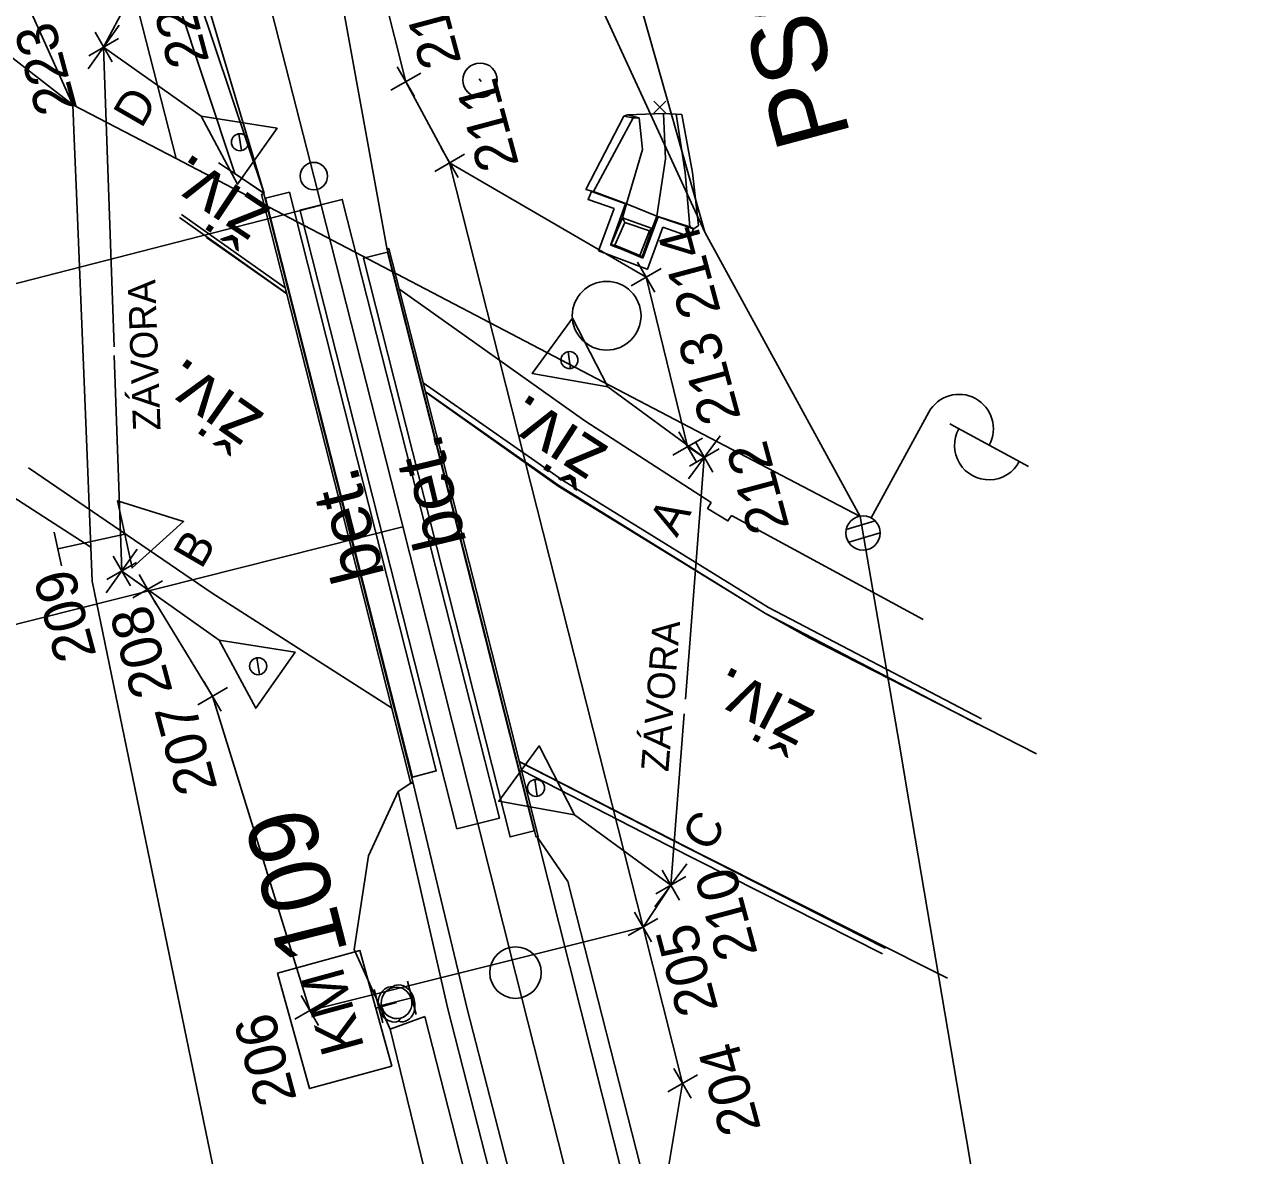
# Model space of a CAD drawing. Extents: x -754679 to -754173, y -1169241 to -1168288.
# Drawn here: x -754521.78 to -754486.32, y -1168479.14 to -1168446.2 of the extents above; entities that cross this region are included whole.
import ezdxf

# ---------------------------------------------------------------- set-up
doc = ezdxf.new("R2010")
doc.units = 0
for name, color, linetype in [('Vrstva 1', 7, 'Continuous'), ('Vrstva 11', 7, 'Continuous'), ('Vrstva 12', 7, 'Continuous'), ('Vrstva 16', 7, 'Continuous'), ('Vrstva 19', 7, 'Continuous'), ('Vrstva 25', 7, 'Continuous'), ('Vrstva 3', 7, 'Continuous'), ('Vrstva 36', 7, 'Continuous'), ('Vrstva 4', 7, 'Continuous'), ('Vrstva 43', 7, 'Continuous'), ('Vrstva 45', 7, 'Continuous'), ('Vrstva 49', 7, 'Continuous'), ('Vrstva 51', 7, 'Continuous'), ('Vrstva 53', 7, 'Continuous'), ('Vrstva 55', 7, 'Continuous'), ('Vrstva 6', 7, 'Continuous'), ('Vrstva 60', 7, 'Continuous'), ('Vrstva 7', 7, 'Continuous')]:
    doc.layers.add(name, color=color, linetype=linetype)

msp = doc.modelspace()

# ---------------------------------------------------------------- linework, layer by layer
at = {"layer": 'Vrstva 1'}
msp.add_line((-754513.137, -1168451.466), (-754513.352, -1168450.618), dxfattribs=at)
for points in [[(-754513.352, -1168450.618), (-754515.29, -1168443.036), (-754517.542, -1168434.317), (-754517.919, -1168432.843), (-754519.829, -1168425.595), (-754522.159, -1168416.85), (-754524.525, -1168408.114), (-754526.908, -1168399.431), (-754528.183, -1168394.853), (-754528.892, -1168392.323), (-754531.158, -1168384.271), (-754532.075, -1168381.055)], [(-754519.168, -1168455.593), (-754519.47, -1168446.863)], [(-754498.393, -1168509.746), (-754500.095, -1168502.999), (-754500.372, -1168501.892), (-754500.594, -1168501.052), (-754502.803, -1168492.326), (-754502.981, -1168491.622), (-754505.012, -1168483.589), (-754507.469, -1168473.859), (-754508.579, -1168469.465), (-754510.811, -1168460.627), (-754513.137, -1168451.466)], [(-754518.943, -1168462.117), (-754519.16, -1168455.846)], [(-754502.538, -1168465.845), (-754501.988, -1168458.809)], [(-754502.962, -1168471.262), (-754502.572, -1168466.271)]]:
    msp.add_lwpolyline(points, dxfattribs=at)
msp.add_circle((-754513.352, -1168450.618), 0.4, dxfattribs=at)
at = {"layer": 'Vrstva 11'}
for p, q in [((-754510.623, -1168474.056), (-754510.378, -1168475.025)), ((-754511.592, -1168474.301), (-754511.347, -1168475.27)), ((-754510.5, -1168474.54), (-754511.47, -1168474.786))]:
    msp.add_line(p, q, dxfattribs=at)
at = {"layer": 'Vrstva 12'}
for p, q in [((-754511.066, -1168474.219), (-754511.047, -1168474.24)), ((-754511.379, -1168474.792), (-754511.468, -1168474.812)), ((-754510.441, -1168474.553), (-754510.512, -1168474.574)), ((-754510.887, -1168475.224), (-754510.832, -1168475.134))]:
    msp.add_line(p, q, dxfattribs=at)
for centre, major_axis, ratio, start_param, end_param in [((-754510.835, -1168474.701), (0.12, -0.53), 0.771425, 5.875182, 9.712717), ((-754511.047, -1168474.732), (-0.119, 0.504), 0.826855, 6.048062, 9.524036), ((-754510.932, -1168474.685), (0.273, -0.37), 0.999682, 2.76009, 5.867568), ((-754510.957, -1168474.691), (-0.275, -0.369), 0.999919, 0.916275, 3.979936)]:
    msp.add_ellipse(centre, major_axis=major_axis, ratio=ratio, start_param=start_param, end_param=end_param, dxfattribs=at)
at = {"layer": 'Vrstva 16'}
for p, q in [((-754511.127, -1168475.454), (-754512.179, -1168473.131)), ((-754511.127, -1168475.454), (-754510.126, -1168475.086)), ((-754510.126, -1168475.086), (-754505.572, -1168492.818)), ((-754506.811, -1168493.205), (-754511.127, -1168475.454))]:
    msp.add_line(p, q, dxfattribs=at)
msp.add_lwpolyline([(-754512.179, -1168473.131), (-754511.761, -1168470.408), (-754510.894, -1168468.538)], dxfattribs=at)
at = {"layer": 'Vrstva 19'}
for p, q in [((-754505.44, -1168451.004), (-754504.327, -1168448.871)), ((-754505.208, -1168451.063), (-754504.058, -1168448.925)), ((-754504.327, -1168448.871), (-754504.222, -1168448.832)), ((-754504.058, -1168448.925), (-754504.327, -1168448.871)), ((-754503.175, -1168448.797), (-754504.222, -1168448.832)), ((-754504.222, -1168448.832), (-754503.885, -1168448.92)), ((-754504.058, -1168448.925), (-754503.885, -1168448.92)), ((-754503.783, -1168449.845), (-754503.885, -1168448.92)), ((-754502.806, -1168448.814), (-754503.175, -1168448.797)), ((-754503.115, -1168450.12), (-754503.175, -1168448.797)), ((-754502.64, -1168448.824), (-754503.175, -1168448.797)), ((-754502.549, -1168450.509), (-754502.806, -1168448.814)), ((-754502.64, -1168448.824), (-754502.806, -1168448.814)), ((-754502.334, -1168450.518), (-754502.64, -1168448.824)), ((-754504.248, -1168451.425), (-754503.783, -1168449.845)), ((-754503.368, -1168451.781), (-754503.115, -1168450.12)), ((-754502.41, -1168452.1), (-754502.549, -1168450.509)), ((-754502.161, -1168452.059), (-754502.334, -1168450.518)), ((-754505.272, -1168451.065), (-754505.292, -1168451.049)), ((-754505.208, -1168451.063), (-754504.248, -1168451.425)), ((-754513.137, -1168451.466), (-754572.704, -1168466.762)), ((-754504.367, -1168451.831), (-754504.248, -1168451.425)), ((-754504.286, -1168451.422), (-754504.248, -1168451.425)), ((-754505.069, -1168452.793), (-754504.616, -1168451.557)), ((-754503.33, -1168451.806), (-754503.368, -1168451.781)), ((-754502.41, -1168452.1), (-754503.368, -1168451.781)), ((-754504.367, -1168451.831), (-754504.298, -1168451.971)), ((-754503.644, -1168453.331), (-754503.196, -1168452.104)), ((-754503.506, -1168452.14), (-754503.582, -1168452.211)), ((-754502.307, -1168452.158), (-754502.288, -1168452.149)), ((-754504.706, -1168452.607), (-754503.78, -1168453.009)), ((-754504.706, -1168452.607), (-754504.704, -1168452.627)), ((-754504.704, -1168452.627), (-754504.595, -1168452.631))]:
    msp.add_line(p, q, dxfattribs=at)
for points in [[(-754505.208, -1168451.063), (-754505.292, -1168451.049), (-754505.44, -1168451.004)], [(-754504.616, -1168451.557), (-754505.371, -1168451.304), (-754505.272, -1168451.065), (-754504.286, -1168451.422), (-754504.706, -1168452.607)], [(-754503.506, -1168452.14), (-754503.368, -1168451.781), (-754504.248, -1168451.425)], [(-754503.78, -1168453.009), (-754503.33, -1168451.806), (-754502.307, -1168452.158), (-754502.401, -1168452.389), (-754502.402, -1168452.389), (-754503.196, -1168452.104)], [(-754504.704, -1168452.627), (-754504.367, -1168451.831), (-754503.506, -1168452.14), (-754503.799, -1168452.967), (-754504.704, -1168452.627)], [(-754504.595, -1168452.631), (-754504.298, -1168451.971), (-754503.582, -1168452.211), (-754503.863, -1168452.93), (-754504.209, -1168452.783), (-754504.595, -1168452.631)], [(-754502.41, -1168452.1), (-754502.288, -1168452.149), (-754502.161, -1168452.059)], [(-754505.069, -1168452.793), (-754503.65, -1168453.33), (-754503.644, -1168453.331)], [(-754503.78, -1168453.009), (-754503.799, -1168452.967), (-754503.863, -1168452.93)]]:
    msp.add_lwpolyline(points, dxfattribs=at)
at = {"layer": 'Vrstva 25'}
for p, q in [((-754497.128, -1168460.568), (-754495.455, -1168457.494)), ((-754494.84, -1168457.828), (-754492.556, -1168459.071)), ((-754497.857, -1168460.907), (-754497.013, -1168460.658)), ((-754497.786, -1168461.277), (-754496.868, -1168461.006))]:
    msp.add_line(p, q, dxfattribs=at)
msp.add_circle((-754497.367, -1168461.007), 0.5, dxfattribs=at)
for centre, start, end in [((-754494.576, -1168457.972), 331.4393, 151.4393), ((-754493.704, -1168458.461), 150.7367, 332.1418)]:
    msp.add_arc(centre, 1, start, end, dxfattribs=at)
at = {"layer": 'Vrstva 36'}
msp.add_line((-754508.542, -1168447.784), (-754508.486, -1168447.868), dxfattribs=at)
msp.add_circle((-754508.514, -1168447.826), 0.5, dxfattribs=at)
at = {"layer": 'Vrstva 4'}
for p, q in [((-754515.654, -1168450.546), (-754518.061, -1168443.282)), ((-754517.46, -1168443.166), (-754514.802, -1168451.124)), ((-754514.802, -1168451.124), (-754517.175, -1168443.155)), ((-754511.222, -1168452.767), (-754512.57, -1168445.306)), ((-754519.019, -1168446.229), (-754519.921, -1168447.497)), ((-754515.539, -1168449.392), (-754515.46, -1168449.875)), ((-754514.802, -1168451.124), (-754515.654, -1168450.546)), ((-754505.878, -1168456.217), (-754505.949, -1168455.733)), ((-754502.449, -1168459.435), (-754501.527, -1168458.183)), ((-754510.761, -1168460.826), (-754571.045, -1168476.051)), ((-754518.492, -1168461.483), (-754519.394, -1168462.751)), ((-754515.011, -1168464.645), (-754514.932, -1168465.128)), ((-754510.894, -1168468.538), (-754510.47, -1168468.256)), ((-754508.877, -1168474.898), (-754510.47, -1168468.256)), ((-754506.852, -1168468.67), (-754506.923, -1168468.186)), ((-754509.455, -1168474.862), (-754510.894, -1168468.538)), ((-754501.401, -1168491.431), (-754506.855, -1168469.858)), ((-754505.958, -1168471.152), (-754506.855, -1168469.858)), ((-754503.423, -1168471.888), (-754502.501, -1168470.636)), ((-754500.851, -1168491.229), (-754505.958, -1168471.152)), ((-754504.93, -1168492.552), (-754509.455, -1168474.862)), ((-754508.877, -1168474.898), (-754504.388, -1168492.293))]:
    msp.add_line(p, q, dxfattribs=at)
for points in [[(-754519.47, -1168446.863), (-754516.631, -1168448.871), (-754514.424, -1168449.224), (-754515.573, -1168450.858), (-754516.631, -1168448.871)], [(-754514.064, -1168451.087), (-754514.759, -1168451.264), (-754514.759, -1168451.265), (-754510.485, -1168468.114), (-754509.79, -1168467.936), (-754514.064, -1168451.087)], [(-754510.525, -1168468.304), (-754510.462, -1168468.293), (-754512.507, -1168460.209), (-754514.812, -1168451.138), (-754514.871, -1168451.152), (-754512.595, -1168460.123), (-754510.525, -1168468.304)], [(-754509.192, -1168469.618), (-754507.951, -1168469.31), (-754512.524, -1168451.299), (-754513.757, -1168451.606), (-754513.753, -1168451.627), (-754509.192, -1168469.618)], [(-754511.21, -1168452.835), (-754511.91, -1168453.004), (-754507.639, -1168469.854), (-754506.942, -1168469.68), (-754511.21, -1168452.835)], [(-754506.88, -1168469.859), (-754506.819, -1168469.846), (-754508.622, -1168462.701), (-754511.166, -1168452.727), (-754511.217, -1168452.745), (-754508.693, -1168462.685), (-754506.88, -1168469.859)], [(-754501.988, -1168458.809), (-754504.794, -1168456.756), (-754506.996, -1168456.367), (-754505.82, -1168454.752), (-754504.794, -1168456.756)], [(-754518.943, -1168462.117), (-754516.104, -1168464.124), (-754513.896, -1168464.476), (-754515.044, -1168466.111), (-754516.104, -1168464.124)], [(-754502.962, -1168471.262), (-754505.768, -1168469.209), (-754507.97, -1168468.82), (-754506.794, -1168467.205), (-754505.768, -1168469.209)]]:
    msp.add_lwpolyline(points, dxfattribs=at)
for centre in [(-754515.501, -1168449.633), (-754505.912, -1168455.975), (-754514.973, -1168464.886), (-754506.886, -1168468.428)]:
    msp.add_circle(centre, 0.248, dxfattribs=at)
at = {"layer": 'Vrstva 43'}
msp.add_circle((-754504.83, -1168454.685), 1, dxfattribs=at)
at = {"layer": 'Vrstva 45'}
msp.add_line((-754503.77, -1168472.48), (-754502.962, -1168471.262), dxfattribs=at)
for points in [[(-754519.47, -1168446.863), (-754518.79, -1168445.56), (-754518.97, -1168444.66), (-754520.27, -1168437.46), (-754528.21, -1168417.88), (-754526.42, -1168417.16), (-754519.52, -1168415.85), (-754514.96, -1168430.83), (-754510.674, -1168447.87), (-754509.4, -1168450.23)], [(-754503.77, -1168472.48), (-754509.4, -1168450.23)], [(-754509.4, -1168450.23), (-754503.68, -1168453.56), (-754502.475, -1168458.494), (-754501.988, -1168458.809)], [(-754518.943, -1168462.117), (-754518.19, -1168462.65), (-754516.3, -1168465.76), (-754513.47, -1168474.91), (-754503.77, -1168472.48)], [(-754503.77, -1168472.48), (-754502.62, -1168477.03), (-754503.11, -1168479.94), (-754501.32, -1168488.67), (-754499.51, -1168488.21)]]:
    msp.add_lwpolyline(points, dxfattribs=at)
at = {"layer": 'Vrstva 49'}
for p, q in [((-754503.46, -1168448.437), (-754503.106, -1168448.791)), ((-754503.46, -1168448.791), (-754503.106, -1168448.437))]:
    msp.add_line(p, q, dxfattribs=at)
at = {"layer": 'Vrstva 51'}
for p, q in [((-754514.831, -1168451.097), (-754516.13, -1168450.231)), ((-754514.831, -1168451.097), (-754514.812, -1168451.138)), ((-754501.194, -1168460.498), (-754495.622, -1168463.531)), ((-754520.912, -1168460.982), (-754520.7, -1168461.96))]:
    msp.add_line(p, q, dxfattribs=at)
for points in [[(-754517.203, -1168451.737), (-754514.186, -1168453.871), (-754514.18, -1168453.875)], [(-754514.139, -1168454.038), (-754514.159, -1168454.024), (-754517.267, -1168451.823)], [(-754514.134, -1168454.056), (-754514.143, -1168454.05), (-754516.478, -1168452.408)], [(-754501.194, -1168460.498), (-754501.303, -1168460.657), (-754501.894, -1168460.295), (-754501.793, -1168460.124), (-754505.467, -1168457.747), (-754510.846, -1168453.919), (-754510.866, -1168453.905)], [(-754510.168, -1168456.64), (-754510.166, -1168456.641), (-754506.113, -1168459.475), (-754500.115, -1168463.173), (-754493.922, -1168466.417)], [(-754510.104, -1168456.89), (-754510.079, -1168456.908), (-754506.223, -1168459.626), (-754500.205, -1168463.351), (-754494.01, -1168466.581)], [(-754492.319, -1168467.439), (-754498.917, -1168464.067), (-754500.205, -1168463.351), (-754506.239, -1168459.644), (-754510.08, -1168456.916), (-754510.101, -1168456.901)], [(-754511.095, -1168466.101), (-754516.313, -1168462.758), (-754521.654, -1168459.115)], [(-754520.806, -1168461.471), (-754518.851, -1168461.047), (-754518.64, -1168462.025), (-754517.141, -1168460.677), (-754519.063, -1168460.07), (-754518.851, -1168461.047)], [(-754507.371, -1168467.66), (-754507.359, -1168467.666), (-754502.077, -1168470.365), (-754494.911, -1168473.97)], [(-754507.368, -1168467.672), (-754507.346, -1168467.683), (-754502.974, -1168469.92), (-754496.721, -1168473.091), (-754496.723, -1168473.091)], [(-754507.308, -1168467.91), (-754507.292, -1168467.918), (-754503.059, -1168470.092), (-754496.806, -1168473.256)]]:
    msp.add_lwpolyline(points, dxfattribs=at)
at = {"layer": 'Vrstva 53'}
for p, q in [((-754516.22, -1168402.04), (-754501.97, -1168452.25)), ((-754520.37, -1168448.54), (-754569.24, -1168410.61)), ((-754520.33, -1168449.52), (-754520.37, -1168448.54)), ((-754520.25, -1168451.35), (-754520.33, -1168449.52)), ((-754519.95, -1168458.75), (-754520.25, -1168451.35)), ((-754501.97, -1168452.25), (-754497.45, -1168460.53)), ((-754533.3, -1168452.78), (-754519.84, -1168461.42)), ((-754519.84, -1168461.42), (-754519.95, -1168458.75)), ((-754497.45, -1168460.53), (-754496.32, -1168467.13)), ((-754496.32, -1168467.13), (-754496.03, -1168468.86)), ((-754496.03, -1168468.86), (-754494.55, -1168477.55)), ((-754494.55, -1168477.55), (-754494.32, -1168478.89)), ((-754494.32, -1168478.89), (-754493.82, -1168481.8))]:
    msp.add_line(p, q, dxfattribs=at)
at = {"layer": 'Vrstva 55'}
for p, q in [((-754517.36, -1168450.11), (-754535.97, -1168376.96)), ((-754525.37, -1168437.38), (-754520.37, -1168448.54)), ((-754506.68, -1168442.02), (-754501.97, -1168452.25)), ((-754520.37, -1168448.54), (-754517.36, -1168450.11)), ((-754517.36, -1168450.11), (-754497.45, -1168460.53)), ((-754519.8, -1168462.41), (-754519.84, -1168461.42)), ((-754486.32, -1168624.94), (-754519.8, -1168462.41))]:
    msp.add_line(p, q, dxfattribs=at)
at = {"layer": 'Vrstva 6'}
for p, q in [((-754519.22, -1168447.296), (-754519.72, -1168446.43)), ((-754519.037, -1168446.613), (-754519.903, -1168447.113)), ((-754510.424, -1168448.303), (-754510.924, -1168447.437)), ((-754510.241, -1168447.62), (-754511.107, -1168448.12)), ((-754508.967, -1168449.98), (-754509.833, -1168450.48)), ((-754509.15, -1168450.663), (-754509.65, -1168449.797)), ((-754503.43, -1168453.993), (-754503.93, -1168453.127)), ((-754503.247, -1168453.31), (-754504.113, -1168453.81)), ((-754502.225, -1168458.927), (-754502.725, -1168458.061)), ((-754502.042, -1168458.244), (-754502.908, -1168458.744)), ((-754501.555, -1168458.559), (-754502.421, -1168459.059)), ((-754501.738, -1168459.242), (-754502.238, -1168458.376)), ((-754518.693, -1168462.55), (-754519.193, -1168461.684)), ((-754518.51, -1168461.867), (-754519.376, -1168462.367)), ((-754517.757, -1168462.4), (-754518.623, -1168462.9)), ((-754517.94, -1168463.083), (-754518.44, -1168462.217)), ((-754515.867, -1168465.51), (-754516.733, -1168466.01)), ((-754516.05, -1168466.193), (-754516.55, -1168465.327)), ((-754502.712, -1168471.695), (-754503.212, -1168470.829)), ((-754502.529, -1168471.012), (-754503.395, -1168471.512)), ((-754503.337, -1168472.23), (-754504.203, -1168472.73)), ((-754503.52, -1168472.913), (-754504.02, -1168472.047)), ((-754513.22, -1168475.343), (-754513.72, -1168474.477)), ((-754513.037, -1168474.66), (-754513.903, -1168475.16)), ((-754502.37, -1168477.463), (-754502.87, -1168476.597)), ((-754502.187, -1168476.78), (-754503.053, -1168477.28))]:
    msp.add_line(p, q, dxfattribs=at)
at = {"layer": 'Vrstva 7'}
msp.add_line((-754510.948, -1168474.681), (-754511.549, -1168474.846), dxfattribs=at)
msp.add_lwpolyline([(-754511.087, -1168476.526), (-754513.481, -1168477.185), (-754514.406, -1168473.822), (-754512.012, -1168473.163)], close=True, dxfattribs=at)
msp.add_circle((-754507.483, -1168473.806), 0.75, dxfattribs=at)

# ---------------------------------------------------------------- texts
at = {"layer": 'Vrstva 11'}
msp.add_text('109', height=2, rotation=104.1901, dxfattribs=at).set_placement((-754512.354, -1168473.201))
at = {"layer": 'Vrstva 3'}
msp.add_text('PS02', height=2.16, rotation=105, dxfattribs=at).set_placement((-754497.721, -1168449.436))
at = {"layer": 'Vrstva 4'}
for s, height, rotation, p in [('D', 1, 60, (-754518.368, -1168449.26)), ('ZÁVORA', 0.8, 92.0732, (-754517.812, -1168458.017)), ('bet.', 1.5, 103.5731, (-754508.902, -1168461.286)), ('bet.', 1.5, 104.2881, (-754511.287, -1168462.235)), ('A', 1, 60, (-754502.79, -1168461.162)), ('B', 1, 60, (-754516.624, -1168462.09)), ('ZÁVORA', 0.8, 85.5249, (-754503.034, -1168467.974)), ('C', 1, 60, (-754501.819, -1168470.335))]:
    msp.add_text(s, height=height, rotation=rotation, dxfattribs=at).set_placement(p)
at = {"layer": 'Vrstva 51'}
for rotation, p in [(146.3099, (-754514.538, -1168451.581)), (144.8847, (-754514.736, -1168457.573)), (147.098, (-754504.715, -1168458.537)), (152.9301, (-754498.693, -1168466.22))]:
    msp.add_text('živ.', height=1.5, rotation=rotation, dxfattribs=at).set_placement(p)
at = {"layer": 'Vrstva 60'}
for s, p in [('222', (-754516.39, -1168447.267)), ('215', (-754509.052, -1168447.296)), ('223', (-754520.234, -1168448.643)), ('211', (-754507.376, -1168450.282)), ('214', (-754501.503, -1168454.563)), ('213', (-754500.919, -1168457.657)), ('212', (-754499.505, -1168460.839)), ('209', (-754519.674, -1168464.565)), ('208', (-754517.454, -1168465.618)), ('207', (-754516.151, -1168468.435)), ('210', (-754500.43, -1168473.252)), ('205', (-754501.574, -1168474.877)), ('206', (-754513.842, -1168477.489)), ('204', (-754500.332, -1168478.351))]:
    msp.add_text(s, height=1.2, rotation=105, dxfattribs=at).set_placement(p)
at = {"layer": 'Vrstva 7'}
msp.add_text('KM', height=1.2469, rotation=105.3838, dxfattribs=at).set_placement((-754511.876, -1168475.991))

doc.saveas('drawing.dxf')
